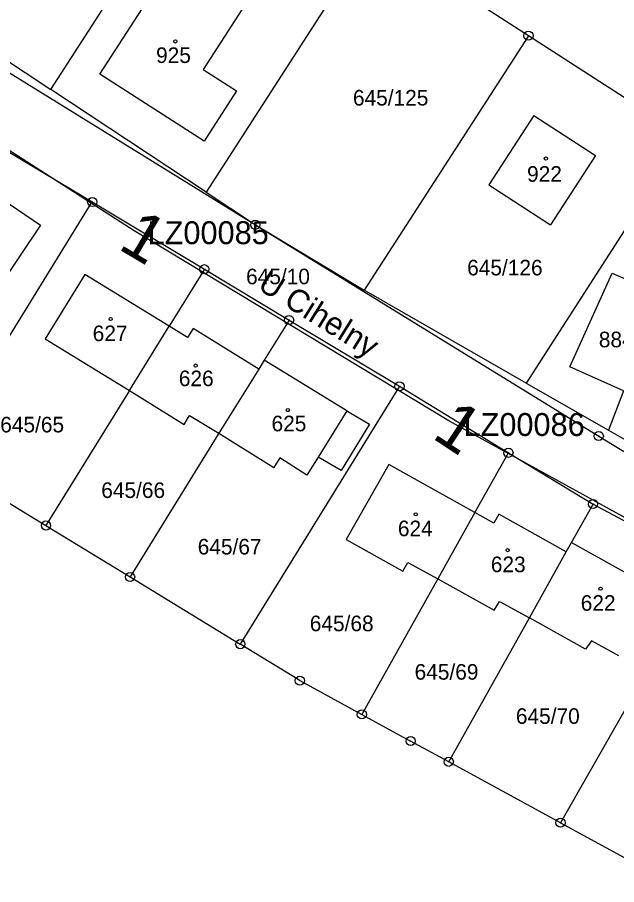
# Model space of a CAD drawing. Extents: x -738131 to -734179, y -1033447 to -1030078.
# Drawn here: x -736171.2 to -736106, y -1032906.8 to -1032812.2 of the extents above; entities that cross this region are included whole.
import ezdxf

# ---------------------------------------------------------------- set-up
doc = ezdxf.new("R2010")
doc.units = 0
for name, color, linetype in [('ftf_2010', 7, 'Continuous'), ('ftf_3010', 7, 'Continuous'), ('ftf_3010_ftf_3010_gtda_3015_gtda_3015_1', 7, 'Continuous'), ('ftf_nu', 7, 'Continuous'), ('Vrstva 1', 7, 'Continuous'), ('Vrstva 2', 7, 'Continuous'), ('Vrstva 4', 7, 'Continuous'), ('Vrstva 5', 7, 'Continuous'), ('Vrstva 8', 7, 'Continuous')]:
    doc.layers.add(name, color=color, linetype=linetype)

msp = doc.modelspace()

# ---------------------------------------------------------------- linework, layer by layer
at = {"layer": 'ftf_2010'}
for points in [[(-736158.511, -1032835.503), (-736189.567, -1032815.567)], [(-736124.231, -1032856.212), (-736158.511, -1032835.503)], [(-736087.777, -1032876.287), (-736124.231, -1032856.212)]]:
    msp.add_lwpolyline(points, dxfattribs=at)
at = {"layer": 'Vrstva 1'}
for points in [[(-736167.59, -1032820.09), (-736149.67, -1032792.27)], [(-736132.63, -1032803.24), (-736150.68, -1032831.29)], [(-736184.5, -1032808.88), (-736167.59, -1032820.09)], [(-736115.57, -1032814.24), (-736123.58, -1032809.07)], [(-736162.26, -1032818.42), (-736157.23, -1032810.7)], [(-736146.75, -1032811.36), (-736150.99, -1032817.92)], [(-736115.57, -1032814.24), (-736133.48, -1032841.99)], [(-736104.51, -1032821.36), (-736115.57, -1032814.24)], [(-736176.22, -1032815.75), (-736145.31, -1032834.85)], [(-736150.99, -1032817.92), (-736147.38, -1032820.23)], [(-736150.9, -1032825.72), (-736162.26, -1032818.42)], [(-736150.68, -1032831.29), (-736167.59, -1032820.09)], [(-736147.38, -1032820.23), (-736150.9, -1032825.72)], [(-736114.99, -1032822.94), (-736119.89, -1032830.51)], [(-736114.99, -1032822.94), (-736108.25, -1032827.3)], [(-736174.89, -1032825.31), (-736163.08, -1032832.36)], [(-736098.52, -1032825.23), (-736115.82, -1032852.13)], [(-736108.25, -1032827.3), (-736113.15, -1032834.86)], [(-736175.48, -1032830.31), (-736168.72, -1032834.88)], [(-736150.68, -1032831.29), (-736145.31, -1032834.85)], [(-736119.89, -1032830.51), (-736113.15, -1032834.86)], [(-736180.26, -1032860.22), (-736163.08, -1032832.36)], [(-736163.08, -1032832.36), (-736150.87, -1032839.7)], [(-736168.72, -1032834.88), (-736173.32, -1032841.73)], [(-736145.31, -1032834.85), (-736133.48, -1032841.99)], [(-736145.31, -1032834.85), (-736107.91, -1032857.89)], [(-736150.87, -1032839.7), (-736154.7, -1032845.92)], [(-736150.87, -1032839.7), (-736141.64, -1032845.24)], [(-736163.88, -1032840.26), (-736168.2, -1032847.29)], [(-736154.7, -1032845.92), (-736163.88, -1032840.26)], [(-736111.05, -1032850.35), (-736106.46, -1032840.13)], [(-736106.46, -1032840.13), (-736100.64, -1032842.69)], [(-736115.82, -1032852.13), (-736133.48, -1032841.99)], [(-736141.64, -1032845.24), (-736144.34, -1032849.62)], [(-736141.64, -1032845.24), (-736129.62, -1032852.46)], [(-736159.04, -1032852.92), (-736154.7, -1032845.92)], [(-736168.2, -1032847.29), (-736159.04, -1032852.92)], [(-736144.34, -1032849.62), (-736144.92, -1032850.59)], [(-736135.35, -1032855.14), (-736144.34, -1032849.62)], [(-736144.92, -1032850.59), (-736149.3, -1032857.59)], [(-736105.21, -1032852.97), (-736111.05, -1032850.35)], [(-736115.82, -1032852.13), (-736106.84, -1032857.26)], [(-736159.04, -1032852.92), (-736168.12, -1032867.64)], [(-736159.04, -1032852.92), (-736153.06, -1032856.63)], [(-736129.62, -1032852.46), (-736146.96, -1032880.58)], [(-736129.62, -1032852.46), (-736117.75, -1032859.71)], [(-736105.21, -1032852.97), (-736106.84, -1032857.26)], [(-736153.06, -1032856.63), (-736152.47, -1032855.65)], [(-736152.47, -1032855.65), (-736149.3, -1032857.59)], [(-736135.35, -1032855.14), (-736132.89, -1032856.6)], [(-736132.89, -1032856.6), (-736135.98, -1032861.64)], [(-736149.3, -1032857.59), (-736158.96, -1032873.25)], [(-736149.3, -1032857.59), (-736143.3, -1032861.3)], [(-736106.84, -1032857.26), (-736098.21, -1032862.2)], [(-736107.91, -1032857.89), (-736104.75, -1032859.84)], [(-736121.41, -1032866.24), (-736117.75, -1032859.71)], [(-736117.75, -1032859.71), (-736108.53, -1032865.3)], [(-736180.26, -1032860.22), (-736168.12, -1032867.64)], [(-736142.66, -1032860.28), (-736143.3, -1032861.3)], [(-736139.69, -1032862.16), (-736142.66, -1032860.28)], [(-736138.47, -1032860.19), (-736139.69, -1032862.16)], [(-736135.98, -1032861.64), (-736138.47, -1032860.19)], [(-736130.79, -1032860.98), (-736135.44, -1032869.18)], [(-736121.41, -1032866.24), (-736130.79, -1032860.98)], [(-736110.87, -1032869.49), (-736108.53, -1032865.3)], [(-736108.53, -1032865.3), (-736096.07, -1032871.97)], [(-736121.41, -1032866.24), (-736125.45, -1032873.46)], [(-736168.12, -1032867.64), (-736158.96, -1032873.25)], [(-736135.44, -1032869.18), (-736129.26, -1032872.62)], [(-736111.45, -1032870.51), (-736110.87, -1032869.49)], [(-736110.87, -1032869.49), (-736101.71, -1032874.62)], [(-736115.47, -1032877.7), (-736111.45, -1032870.51)], [(-736129.26, -1032872.62), (-736128.69, -1032871.66)], [(-736128.69, -1032871.66), (-736125.45, -1032873.46)], [(-736096.07, -1032871.97), (-736112.08, -1032900.05)], [(-736158.96, -1032873.25), (-736146.96, -1032880.58)], [(-736125.45, -1032873.46), (-736133.72, -1032888.23)], [(-736125.45, -1032873.46), (-736119.3, -1032876.89)], [(-736119.3, -1032876.89), (-736118.71, -1032875.92)], [(-736118.71, -1032875.92), (-736115.47, -1032877.7)], [(-736124.25, -1032893.4), (-736115.47, -1032877.7)], [(-736109.37, -1032881.13), (-736115.47, -1032877.7)], [(-736108.69, -1032880.22), (-736109.37, -1032881.13)], [(-736105.71, -1032881.85), (-736108.69, -1032880.22)], [(-736140.47, -1032884.55), (-736146.96, -1032880.58)], [(-736140.47, -1032884.55), (-736133.72, -1032888.23)], [(-736133.72, -1032888.23), (-736128.4, -1032891.14)], [(-736124.25, -1032893.4), (-736128.4, -1032891.14)], [(-736112.08, -1032900.05), (-736124.25, -1032893.4)], [(-736112.08, -1032900.05), (-736099.72, -1032906.8)]]:
    msp.add_lwpolyline(points, dxfattribs=at)
at = {"layer": 'Vrstva 4'}
for points in [[(-736152.71, -1032847.15), (-736154.7, -1032845.92)], [(-736152.09, -1032846.16), (-736152.71, -1032847.15)], [(-736144.92, -1032850.59), (-736152.09, -1032846.16)], [(-736135.35, -1032855.14), (-736138.47, -1032860.19)], [(-736119.35, -1032867.39), (-736121.41, -1032866.24)], [(-736118.78, -1032866.41), (-736119.35, -1032867.39)], [(-736111.45, -1032870.51), (-736118.78, -1032866.41)]]:
    msp.add_lwpolyline(points, dxfattribs=at)
at = {"layer": 'Vrstva 5'}
for centre in [(-736154.027, -1032814.859), (-736113.667, -1032827.629), (-736161.077, -1032845.129), (-736151.817, -1032850.199), (-736141.777, -1032855.059), (-736127.847, -1032866.429), (-736117.837, -1032870.329), (-736107.717, -1032874.529)]:
    msp.add_circle(centre, 0.175, dxfattribs=at)
at = {"layer": 'Vrstva 8'}
for centre, radius in [((-736115.57, -1032814.24), 0.5), ((-736115.57, -1032814.24), 0.0303), ((-736163.08, -1032832.36), 0.5), ((-736163.08, -1032832.36), 0.0303), ((-736145.31, -1032834.85), 0.5), ((-736145.31, -1032834.85), 0.0303), ((-736150.87, -1032839.7), 0.5), ((-736150.87, -1032839.7), 0.0303), ((-736141.64, -1032845.24), 0.5), ((-736141.64, -1032845.24), 0.0303), ((-736129.62, -1032852.46), 0.5), ((-736129.62, -1032852.46), 0.0303), ((-736107.91, -1032857.89), 0.5), ((-736107.91, -1032857.89), 0.0303), ((-736117.75, -1032859.71), 0.5), ((-736117.75, -1032859.71), 0.0303), ((-736108.53, -1032865.3), 0.5), ((-736108.53, -1032865.3), 0.0303), ((-736168.12, -1032867.64), 0.5), ((-736168.12, -1032867.64), 0.0303), ((-736158.96, -1032873.25), 0.5), ((-736158.96, -1032873.25), 0.0303), ((-736146.96, -1032880.58), 0.5), ((-736146.96, -1032880.58), 0.0303), ((-736140.47, -1032884.55), 0.5), ((-736140.47, -1032884.55), 0.0303), ((-736133.72, -1032888.23), 0.5), ((-736133.72, -1032888.23), 0.0303), ((-736128.4, -1032891.14), 0.5), ((-736128.4, -1032891.14), 0.0303), ((-736124.25, -1032893.4), 0.5), ((-736124.25, -1032893.4), 0.0303), ((-736112.08, -1032900.05), 0.5), ((-736112.08, -1032900.05), 0.0303)]:
    msp.add_circle(centre, radius, dxfattribs=at)

# ---------------------------------------------------------------- texts
at = {"layer": 'ftf_3010'}
for rotation, p in [(329.32366, (-736160.395, -1032837.409)), (326.54061, (-736126.204, -1032858.024))]:
    msp.add_text('1', height=5.2, rotation=rotation, dxfattribs=at).set_placement(p)
at = {"layer": 'ftf_3010_ftf_3010_gtda_3015_gtda_3015_1'}
for s, p in [('LZ00085', (-736157.052, -1032836.968)), ('LZ00086', (-736122.64, -1032857.88))]:
    msp.add_text(s, height=2.5, dxfattribs=at).set_placement(p)
at = {"layer": 'ftf_nu'}
msp.add_text('U Cihelny', height=2.5, rotation=328.12319, dxfattribs=at).set_placement((-736145.196, -1032841.796))
at = {"layer": 'Vrstva 2'}
for s, p in [('925', (-736156.13, -1032817.21)), ('645/125', (-736134.686, -1032821.85)), ('922', (-736115.72, -1032830.16)), ('645/126', (-736122.244, -1032840.37)), ('645/10', (-736146.325, -1032841.34)), ('627', (-736163.034, -1032847.54)), ('884', (-736107.902, -1032848.21)), ('626', (-736153.649, -1032852.45)), ('645/65', (-736173.1, -1032857.49)), ('625', (-736143.55, -1032857.37)), ('645/66', (-736162.098, -1032864.64)), ('624', (-736129.789, -1032868.81)), ('645/67', (-736151.593, -1032870.8)), ('623', (-736119.666, -1032872.73)), ('622', (-736109.874, -1032876.94)), ('645/68', (-736139.386, -1032879.17)), ('645/69', (-736127.968, -1032884.45)), ('645/70', (-736116.937, -1032889.27))]:
    msp.add_text(s, height=1.7, dxfattribs=at).set_placement(p)

doc.saveas('drawing.dxf')
